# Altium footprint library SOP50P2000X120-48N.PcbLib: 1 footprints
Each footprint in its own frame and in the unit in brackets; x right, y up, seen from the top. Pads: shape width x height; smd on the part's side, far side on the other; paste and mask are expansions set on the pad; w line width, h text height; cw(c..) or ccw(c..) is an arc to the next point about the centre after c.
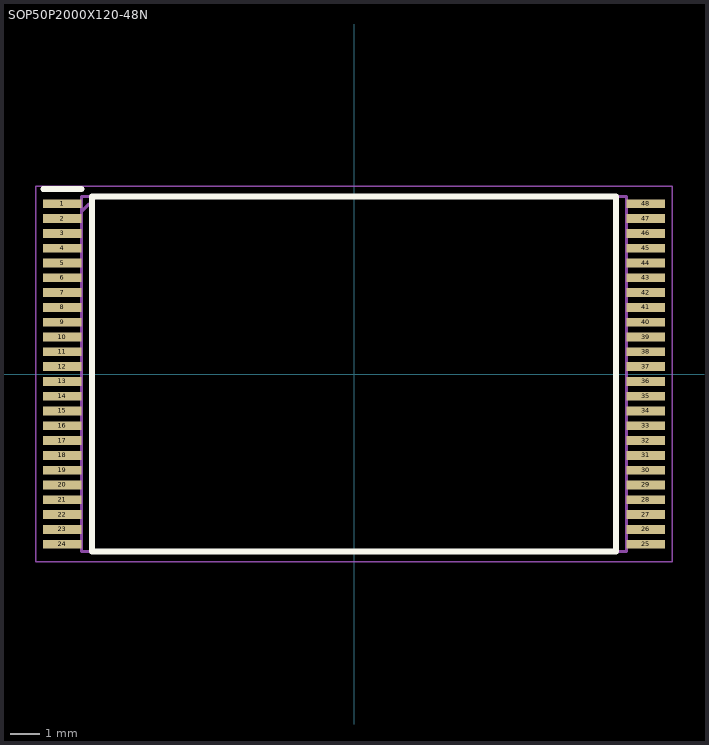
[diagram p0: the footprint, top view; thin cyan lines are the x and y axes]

## SOP50P2000X120-48N [mm]
pads (48):
  rect 1.3x0.3 smd: 1(-9.85,5.75) 2(-9.85,5.25) 3(-9.85,4.75) 4(-9.85,4.25) 5(-9.85,3.75) 6(-9.85,3.25) 7(-9.85,2.75) 8(-9.85,2.25) 9(-9.85,1.75) 10(-9.85,1.25) 11(-9.85,0.75) 12(-9.85,0.25) 13(-9.85,-0.25) 14(-9.85,-0.75) 15(-9.85,-1.25) 16(-9.85,-1.75) 17(-9.85,-2.25) 18(-9.85,-2.75) 19(-9.85,-3.25) 20(-9.85,-3.75) 21(-9.85,-4.25) 22(-9.85,-4.75) 23(-9.85,-5.25) 24(-9.85,-5.75) 25(9.85,-5.75) 26(9.85,-5.25) 27(9.85,-4.75) 28(9.85,-4.25) 29(9.85,-3.75) 30(9.85,-3.25) 31(9.85,-2.75) 32(9.85,-2.25) 33(9.85,-1.75) 34(9.85,-1.25) 35(9.85,-0.75) 36(9.85,-0.25) 37(9.85,0.25) 38(9.85,0.75) 39(9.85,1.25) 40(9.85,1.75) 41(9.85,2.25) 42(9.85,2.75) 43(9.85,3.25) 44(9.85,3.75) 45(9.85,4.25) 46(9.85,4.75) 47(9.85,5.25) 48(9.85,5.75)
Top Overlay:
  lines w0.2: -10.5,6.25 -9.2,6.25 ; -8.85,-6 8.85,-6 8.85,6 -8.85,6 -8.85,-6
Mechanical 15:
  lines w0.1: -9.2,5.5 -8.7,6 ; -9.2,-6 9.2,-6 9.2,6 -9.2,6 -9.2,-6
Mechanical 20:
  lines w0.05: -10.75,-6.35 10.75,-6.35 10.75,6.35 -10.75,6.35 -10.75,-6.35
